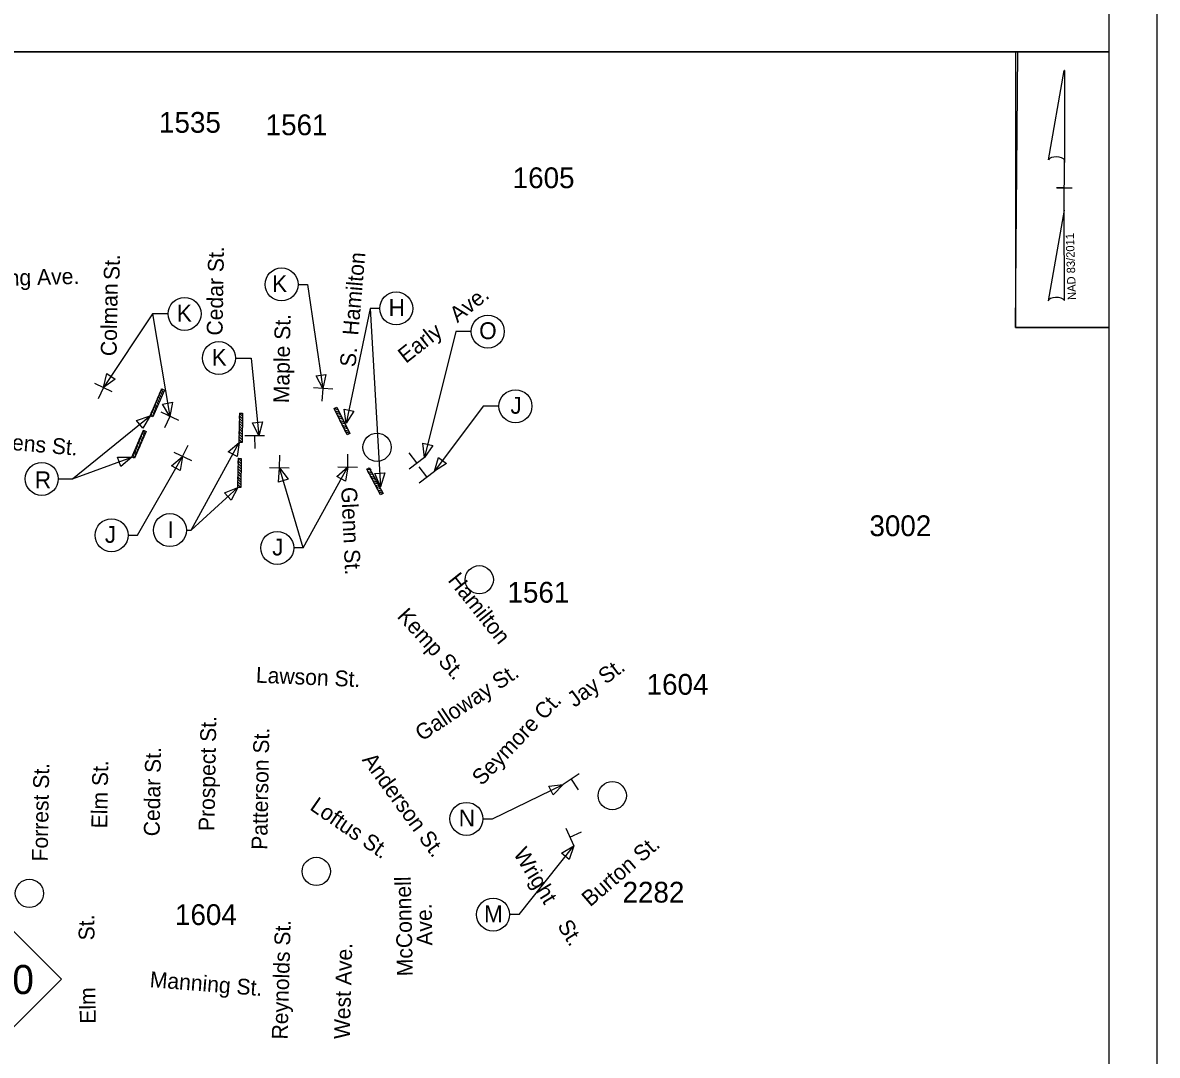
# Model space of a CAD drawing. Extents: x 2157572 to 5059327, y 715220 to 1674494.
# Drawn here: x 2166357 to 2171076, y 724870 to 729165 of the extents above; entities that cross this region are included whole.
import ezdxf

# ---------------------------------------------------------------- set-up
doc = ezdxf.new("R2010")
doc.units = 0
for name, color, linetype in [('Exist Cultural Church Label', 7, 'Continuous'), ('Exist Cultural Recreational Athletic Track', 7, 'Continuous'), ('Exist Road Primary US Shield CELL', 7, 'Continuous'), ('Exist Road Primary US Structure Standard Bridge Number Label', 7, 'Continuous'), ('Exist Road Secondary Type 41 SR Number Label', 7, 'Continuous'), ('Exist Road Secondary Type 51 Divided Label', 7, 'Continuous'), ('Exist Road Secondary Type 51 Undivided 3 Lane Attributed', 7, 'Continuous'), ('Level 51', 7, 'Continuous'), ('Level 53', 7, 'Continuous'), ('Map Preparation County Base Legend Correctional Institution', 7, 'Continuous'), ('Map Preparation County Base Legend Highway Garage or Maintenance Office', 7, 'Continuous'), ('Map Preparation County Base Legend Monument Small Historical Site', 7, 'Continuous'), ('Map Preparation County Base Legend Weight Station', 7, 'Continuous'), ('Map Preparation County North Arrow CELL', 7, 'Continuous'), ('Map Preparation County North Arrow Shadow', 7, 'Continuous'), ('Map Preparation County North Arrow White Shapes', 7, 'Continuous')]:
    doc.layers.add(name, color=color, linetype=linetype)

msp = doc.modelspace()

# ---------------------------------------------------------------- linework, layer by layer
at = {"layer": 'Exist Cultural Church Label'}
for centre in [(2167433.7, 728076), (2167910.5, 727976.1), (2167030.5, 727953.4), (2168291.5, 727880), (2167172.9, 727769.9), (2168406.5, 727569.5), (2166436.2, 727267.1), (2166726.5, 727032.7), (2166969.2, 727054.1), (2167415.6, 726980.1), (2168202.3, 725853.4), (2168313.1, 725455)]:
    msp.add_circle(centre, 68.6, dxfattribs=at)
at = {"layer": 'Exist Road Secondary Type 41 SR Number Label'}
for p, q in [((2166887.1, 727529.6), (2166935.1, 727641.1)), ((2166946.1, 727636.4), (2166898.1, 727524.9)), ((2166917.7, 727601.1), (2166922, 727611.1)), ((2166922, 727611.1), (2166928.4, 727595.3)), ((2166926.3, 727621.2), (2166930.6, 727631.2)), ((2166932.7, 727605.4), (2166926.3, 727621.2)), ((2166930.6, 727631.2), (2166937.1, 727615.4)), ((2166937.1, 727615.4), (2166932.7, 727605.4)), ((2166934.9, 727641.2), (2166946.1, 727636.4)), ((2166941.4, 727625.4), (2166934.9, 727641.2)), ((2166935.1, 727641.1), (2166946.1, 727636.4)), ((2166946.1, 727636.4), (2166941.4, 727625.4)), ((2166900.4, 727560.9), (2166904.7, 727571)), ((2166906.7, 727545), (2166900.4, 727560.9)), ((2166904.7, 727571), (2166911.1, 727555)), ((2166909, 727581), (2166913.3, 727591)), ((2166915.5, 727565.2), (2166909, 727581)), ((2166913.3, 727591), (2166919.8, 727575.2)), ((2166919.8, 727575.2), (2166915.5, 727565.2)), ((2166924.1, 727585.3), (2166917.7, 727601.1)), ((2166928.4, 727595.3), (2166924.1, 727585.3)), ((2167652, 727559.6), (2167662.9, 727565)), ((2167668.2, 727554.3), (2167652, 727559.6)), ((2167652.2, 727559.7), (2167662.9, 727565)), ((2167706.2, 727451), (2167652.2, 727559.7)), ((2167662.9, 727565), (2167668.2, 727554.3)), ((2167662.9, 727565), (2167716.9, 727456.3)), ((2166898.1, 727524.9), (2166887.1, 727529.6)), ((2166891.7, 727540.9), (2166896, 727550.9)), ((2166898.1, 727524.9), (2166891.7, 727540.9)), ((2166896, 727550.9), (2166902.4, 727534.9)), ((2166902.4, 727534.9), (2166898.1, 727524.9)), ((2166911.1, 727555), (2166906.7, 727545)), ((2167257.2, 727419.2), (2167259.6, 727540.6)), ((2167258.9, 727518.8), (2167259.2, 727529.7)), ((2167270.9, 727506.6), (2167258.9, 727518.8)), ((2167259.2, 727529.7), (2167271.1, 727517.5)), ((2167259.4, 727540.7), (2167271.5, 727540.4)), ((2167271.3, 727528.5), (2167259.4, 727540.7)), ((2167259.6, 727540.6), (2167271.5, 727540.4)), ((2167271.5, 727540.4), (2167269.2, 727419)), ((2167271.1, 727517.5), (2167270.9, 727506.6)), ((2167271.5, 727540.4), (2167271.3, 727528.5)), ((2167656.9, 727549.8), (2167673.1, 727544.5)), ((2167661.7, 727540.1), (2167656.9, 727549.8)), ((2167677.9, 727534.8), (2167661.7, 727540.1)), ((2167666.6, 727530.3), (2167682.8, 727525)), ((2167671.5, 727520.5), (2167666.6, 727530.3)), ((2167687.7, 727515.2), (2167671.5, 727520.5)), ((2167673.1, 727544.5), (2167677.9, 727534.8)), ((2167676.3, 727510.7), (2167692.5, 727505.4)), ((2167681.2, 727500.9), (2167676.3, 727510.7)), ((2167682.8, 727525), (2167687.7, 727515.2)), ((2166811.1, 727357.8), (2166859.2, 727469.4)), ((2166870.1, 727464.6), (2166822.1, 727353.1)), ((2166859, 727469.4), (2166870.1, 727464.6)), ((2166865.4, 727453.6), (2166859, 727469.4)), ((2166859.2, 727469.4), (2166870.1, 727464.6)), ((2166870.1, 727464.6), (2166865.4, 727453.6)), ((2167257.7, 727453.3), (2167257.9, 727464.2)), ((2167257.9, 727464.2), (2167269.8, 727451.8)), ((2167258.1, 727475.1), (2167258.3, 727486)), ((2167270, 727462.9), (2167258.1, 727475.1)), ((2167258.3, 727486), (2167270.2, 727473.8)), ((2167258.5, 727497), (2167258.7, 727507.9)), ((2167270.5, 727484.8), (2167258.5, 727497)), ((2167258.7, 727507.9), (2167270.7, 727495.7)), ((2167270.2, 727473.8), (2167270, 727462.9)), ((2167270.7, 727495.7), (2167270.5, 727484.8)), ((2167697.4, 727495.6), (2167681.2, 727500.9)), ((2167686, 727491.1), (2167702.3, 727485.6)), ((2167690.9, 727481.3), (2167686, 727491.1)), ((2167707.2, 727475.9), (2167690.9, 727481.3)), ((2167692.5, 727505.4), (2167697.4, 727495.6)), ((2167695.8, 727471.5), (2167712.1, 727466.1)), ((2167700.6, 727461.8), (2167695.8, 727471.5)), ((2167702.3, 727485.6), (2167707.2, 727475.9)), ((2167712.1, 727466.1), (2167716.9, 727456.3)), ((2166833, 727409.2), (2166837.4, 727419.3)), ((2166837.4, 727419.3), (2166843.8, 727403.5)), ((2166841.7, 727429.3), (2166846, 727439.3)), ((2166848.1, 727413.5), (2166841.7, 727429.3)), ((2166846, 727439.3), (2166852.5, 727423.5)), ((2166852.5, 727423.5), (2166848.1, 727413.5)), ((2166850.3, 727449.4), (2166854.6, 727459.4)), ((2166856.8, 727433.6), (2166850.3, 727449.4)), ((2166854.6, 727459.4), (2166861.1, 727443.6)), ((2166861.1, 727443.6), (2166856.8, 727433.6)), ((2167269.2, 727419), (2167257.2, 727419.2)), ((2167257.3, 727431.4), (2167257.5, 727442.3)), ((2167269.2, 727419), (2167257.3, 727431.4)), ((2167257.5, 727442.3), (2167269.4, 727429.9)), ((2167269.6, 727440.9), (2167257.7, 727453.3)), ((2167269.4, 727429.9), (2167269.2, 727419)), ((2167269.8, 727451.8), (2167269.6, 727440.9)), ((2167716.9, 727456.3), (2167700.6, 727461.8)), ((2167716.9, 727456.3), (2167706.2, 727451)), ((2166815.8, 727369.1), (2166820.1, 727379.1)), ((2166822.1, 727353.1), (2166815.8, 727369.1)), ((2166820.1, 727379.1), (2166826.4, 727363.1)), ((2166824.4, 727389.1), (2166828.7, 727399.2)), ((2166830.8, 727373.2), (2166824.4, 727389.1)), ((2166828.7, 727399.2), (2166835.1, 727383.2)), ((2166835.1, 727383.2), (2166830.8, 727373.2)), ((2166839.5, 727393.4), (2166833, 727409.2)), ((2166843.8, 727403.5), (2166839.5, 727393.4)), ((2166822.1, 727353.1), (2166811.1, 727357.8)), ((2166826.4, 727363.1), (2166822.1, 727353.1)), ((2167251.8, 727231.5), (2167254.1, 727352.9)), ((2167253.5, 727331), (2167253.7, 727342)), ((2167265.4, 727318.9), (2167253.5, 727331)), ((2167253.7, 727342), (2167265.6, 727329.8)), ((2167253.9, 727352.9), (2167266.1, 727352.7)), ((2167265.8, 727340.7), (2167253.9, 727352.9)), ((2167254.1, 727352.9), (2167266.1, 727352.7)), ((2167266.1, 727352.7), (2167263.7, 727231.3)), ((2167265.6, 727329.8), (2167265.4, 727318.9)), ((2167266.1, 727352.7), (2167265.8, 727340.7)), ((2167252.2, 727265.5), (2167252.4, 727276.4)), ((2167252.4, 727276.4), (2167264.4, 727264)), ((2167252.6, 727287.3), (2167252.8, 727298.3)), ((2167264.6, 727275.2), (2167252.6, 727287.3)), ((2167252.8, 727298.3), (2167264.8, 727286.1)), ((2167253.1, 727309.2), (2167253.3, 727320.1)), ((2167265, 727297), (2167253.1, 727309.2)), ((2167253.3, 727320.1), (2167265.2, 727307.9)), ((2167264.8, 727286.1), (2167264.6, 727275.2)), ((2167265.2, 727307.9), (2167265, 727297)), ((2167787.9, 727308.1), (2167798.6, 727313.8)), ((2167804.3, 727303.3), (2167787.9, 727308.1)), ((2167788.1, 727308.2), (2167798.6, 727313.8)), ((2167845.7, 727201.2), (2167788.1, 727308.2)), ((2167793.1, 727298.4), (2167809.5, 727293.7)), ((2167798.3, 727288.8), (2167793.1, 727298.4)), ((2167814.7, 727284.1), (2167798.3, 727288.8)), ((2167798.6, 727313.8), (2167804.3, 727303.3)), ((2167798.6, 727313.8), (2167856.2, 727206.9)), ((2167803.5, 727279.2), (2167819.9, 727274.4)), ((2167808.7, 727269.6), (2167803.5, 727279.2)), ((2167809.5, 727293.7), (2167814.7, 727284.1)), ((2167251.8, 727243.6), (2167252, 727254.6)), ((2167263.7, 727231.3), (2167251.8, 727243.6)), ((2167263.7, 727231.3), (2167251.8, 727231.5)), ((2167252, 727254.6), (2167263.9, 727242.2)), ((2167264.1, 727253.1), (2167252.2, 727265.5)), ((2167263.9, 727242.2), (2167263.7, 727231.3)), ((2167264.4, 727264), (2167264.1, 727253.1)), ((2167825, 727264.8), (2167808.7, 727269.6)), ((2167813.8, 727259.9), (2167830.2, 727255.2)), ((2167819, 727250.3), (2167813.8, 727259.9)), ((2167835.4, 727245.6), (2167819, 727250.3)), ((2167819.9, 727274.4), (2167825, 727264.8)), ((2167824.2, 727240.7), (2167840.7, 727235.8)), ((2167829.4, 727231.1), (2167824.2, 727240.7)), ((2167845.8, 727226.1), (2167829.4, 727231.1)), ((2167830.2, 727255.2), (2167835.4, 727245.6)), ((2167840.7, 727235.8), (2167845.8, 727226.1)), ((2167834.6, 727221.5), (2167851, 727216.5)), ((2167839.7, 727211.8), (2167834.6, 727221.5)), ((2167856.2, 727206.9), (2167839.7, 727211.8)), ((2167856.2, 727206.9), (2167845.7, 727201.2)), ((2167851, 727216.5), (2167856.2, 727206.9))]:
    msp.add_line(p, q, dxfattribs=at)
at = {"layer": 'Exist Road Secondary Type 51 Divided Label'}
msp.add_lwpolyline([(2157571.9, 722288.7), (2171075.9, 722288.7), (2171075.9, 731088.6), (2157571.9, 731088.6)], close=True, dxfattribs=at)
at = {"layer": 'Exist Road Secondary Type 51 Undivided 3 Lane Attributed'}
msp.add_lwpolyline([(2170485.5, 727897.1), (2170495.8, 729042.7), (2158875.9, 729042.7), (2158875.9, 722488.7), (2166434.4, 722488.7), (2166434.4, 723622.8), (2170875.9, 723622.8), (2170875.9, 727897.1)], close=True, dxfattribs=at)
at = {"layer": 'Level 51'}
for p, q in [((2167502.4, 728076), (2167542, 728076)), ((2167542, 728076), (2167605.9, 727643.4)), ((2166896.7, 727953.4), (2166692.9, 727647.1)), ((2166961.9, 727953.4), (2166896.7, 727953.4)), ((2166896.7, 727953.4), (2166969, 727526.9)), ((2167802.2, 727976.1), (2167702.2, 727498.5)), ((2167841.8, 727976.1), (2167802.2, 727976.1)), ((2167802.2, 727976.1), (2167845.8, 727234.9)), ((2168157.8, 727880), (2168028.7, 727357.8)), ((2168222.9, 727880), (2168157.8, 727880)), ((2167241.5, 727769.9), (2167306.7, 727769.9)), ((2167306.7, 727769.9), (2167339.3, 727447)), ((2168272.7, 727569.5), (2168070, 727299.9)), ((2168337.8, 727569.5), (2168272.7, 727569.5)), ((2166563.8, 727267.1), (2166887.1, 727529.6)), ((2167057, 727054.1), (2167257.2, 727419.2)), ((2166563.8, 727267.1), (2166811.1, 727357.8)), ((2166834.7, 727032.7), (2167022.3, 727360.6)), ((2167523.9, 726980.1), (2167424.9, 727313.4)), ((2167523.9, 726980.1), (2167708.7, 727316.9)), ((2166504.9, 727267.1), (2166563.8, 727267.1)), ((2167057, 727054.1), (2167251.8, 727231.5)), ((2167037.8, 727054.1), (2167057, 727054.1)), ((2166795.1, 727032.7), (2166834.7, 727032.7)), ((2167523.9, 726980.1), (2167484.3, 726980.1)), ((2168310.5, 725853.4), (2168604.4, 725995.7)), ((2168270.9, 725853.4), (2168310.5, 725853.4)), ((2168421.4, 725455), (2168648.6, 725741.1)), ((2168421.4, 725455), (2168381.8, 725455))]:
    msp.add_line(p, q, dxfattribs=at)
for points in [[(2166706.4, 727705.3), (2166741.1, 727682.5), (2166692.9, 727647.1)], [(2167577.2, 727695.8), (2167618.2, 727701.8), (2167605.9, 727643.4)], [(2166938.9, 727578.6), (2166979.8, 727585.7), (2166969, 727526.9)], [(2166856.7, 727478.2), (2166830.5, 727510.4), (2166887.1, 727529.6)], [(2167693.4, 727557.6), (2167734, 727549.1), (2167702.2, 727498.5)], [(2167312.8, 727500.5), (2167354, 727504.9), (2167339.3, 727447)], [(2167248.5, 727360.1), (2167212.1, 727380.1), (2167257.2, 727419.2)], [(2168021.8, 727416.2), (2168062.1, 727406.5), (2168028.8, 727356.9)], [(2166765.7, 727319), (2166751.4, 727358), (2166811.1, 727357.8)], [(2167012.5, 727301.6), (2166976.5, 727322.2), (2167022.3, 727360.6)], [(2168086.5, 727356.4), (2168119.8, 727331.6), (2168069.7, 727299)], [(2167460.9, 727265.7), (2167421.2, 727253.7), (2167424.9, 727313.4)], [(2167700.1, 727257.7), (2167663.7, 727277.6), (2167708.7, 727316.9)], [(2167821.8, 727289.6), (2167863.2, 727292), (2167845.8, 727234.9)], [(2167224.3, 727178.4), (2167196.4, 727209.1), (2167251.8, 727231.5)], [(2168563, 725952.6), (2168544.9, 725989.9), (2168604.4, 725995.7)], [(2168630, 725684.3), (2168597.5, 725710.1), (2168648.6, 725741.1)]]:
    msp.add_lwpolyline(points, close=True, dxfattribs=at)
for centre in [(2167830.6, 727398.6), (2168255.9, 726847.7), (2168809.1, 725949.9), (2167578.2, 725634.9), (2166385, 725543.6)]:
    msp.add_circle(centre, 58.7, dxfattribs=at)
at = {"layer": 'Map Preparation County Base Legend Highway Garage or Maintenance Office'}
for centre in [(2167433.7, 728076), (2167910.5, 727976.1), (2167030.5, 727953.4), (2168291.5, 727880), (2167172.9, 727769.9), (2168406.5, 727569.5), (2166436.2, 727267.1), (2166726.5, 727032.7), (2166726.5, 727032.7), (2166969.2, 727054.1), (2167415.6, 726980.1), (2168202.3, 725853.4), (2168313.1, 725455)]:
    msp.add_circle(centre, 68.6, dxfattribs=at)
at = {"layer": 'Map Preparation County Base Legend Monument Small Historical Site'}
msp.add_lwpolyline([(2166058.5, 725186.7), (2166288.7, 725416.9), (2166518.9, 725186.7), (2166288.7, 724956.4)], close=True, dxfattribs=at)
at = {"layer": 'Map Preparation County North Arrow CELL'}
for p, q in [((2170623.4, 728594.8), (2170688.9, 728965)), ((2170689.3, 728965), (2170688.9, 728965)), ((2170689.3, 728965), (2170688.9, 728965)), ((2170689.3, 728965), (2170689.3, 728583.2)), ((2170689.2, 728385.2), (2170689.3, 728594.4)), ((2170689.3, 728583.2), (2170689.3, 728594)), ((2170657.3, 728477.8), (2170656.9, 728477.8)), ((2170685.7, 728477.8), (2170657.3, 728477.8)), ((2170657.7, 728477.8), (2170721.6, 728477.8)), ((2170689.2, 728385.2), (2170622.5, 728007.8)), ((2170689.6, 728009.4), (2170689.2, 728385.2))]:
    msp.add_line(p, q, dxfattribs=at)
for centre, start_param, end_param in [((2170656.4, 728590.9), 0.216388, 2.908219), ((2170656.4, 728006.5), 0.201328, 3.141593)]:
    msp.add_ellipse(centre, major_axis=(33.8, -0.2), ratio=0.461098, start_param=start_param, end_param=end_param, dxfattribs=at)
at = {"layer": 'Map Preparation County North Arrow Shadow'}
for p, q in [((2166729.8, 727629.7), (2166656.6, 727664.2)), ((2166692.9, 727647.1), (2166670.5, 727599.6)), ((2167646.6, 727640), (2167565.9, 727646.6)), ((2167605.9, 727643.4), (2167601.6, 727591)), ((2167005.9, 727509.5), (2166932.7, 727544.1)), ((2166969, 727526.9), (2166946.6, 727479.4)), ((2167362.5, 727446.4), (2167281.5, 727445.9)), ((2167321.7, 727446.1), (2167322, 727393.6)), ((2166985.5, 727378.1), (2167058.6, 727343.3)), ((2167022.3, 727360.6), (2167044.9, 727408)), ((2167708.7, 727316.9), (2167709.6, 727369.4)), ((2167996.7, 727333.5), (2167965, 727375.3)), ((2167424.9, 727313.4), (2167425.8, 727365.8)), ((2167964.1, 727308.9), (2168028.7, 727357.8)), ((2167384.1, 727314.1), (2167465.1, 727312.7)), ((2167667.8, 727317.6), (2167748.8, 727316.2)), ((2168005.4, 727251), (2168070, 727299.9)), ((2168038, 727275.7), (2168006.2, 727317.5)), ((2168672, 726040.4), (2168604.4, 725995.7)), ((2168637.9, 726017.9), (2168666.9, 725974.1)), ((2168616, 725815.2), (2168648.6, 725741.1)), ((2168632.4, 725777.9), (2168680.4, 725799))]:
    msp.add_line(p, q, dxfattribs=at)
at = {"layer": 'Map Preparation County North Arrow White Shapes'}
msp.add_line((2158905.6, 729042.7), (2170875.9, 729042.7), dxfattribs=at)
for points in [[(2170875.9, 730888.7), (2158875.9, 730888.7), (2158875.9, 722488.7), (2170875.9, 722488.7)], [(2170875.9, 729042.7), (2170485.5, 729042.7), (2170485.5, 727897.1), (2170875.9, 727897.1)]]:
    msp.add_lwpolyline(points, close=True, dxfattribs=at)

# ---------------------------------------------------------------- texts
at = {"layer": 'Exist Cultural Recreational Athletic Track'}
for s, height, rotation, p in [('Cedar St.', 65.68, 89.0256, (2167188, 727862.9)), ('St.', 65.68, 89.0256, (2166759.6, 728093.8)), ('Irving Ave.', 65.681, 1.545, (2166178.4, 728067.1)), ('Colman', 65.68, 89.0256, (2166747.4, 727777.4)), ('Early   Ave.', 65.681, 38.263, (2167950.6, 727745.1)), ('Maple St.', 65.68, 89.0256, (2167464.9, 727581.6)), ('Givens St.', 65.68, 355.0653, (2166179.3, 727398.8)), ('Glenn St.', 65.68, 272.6342, (2167681.4, 727232)), ('Kemp St.', 65.68, 312.1703, (2167910.9, 726693.5)), ('Lawson St.', 65.68, 357.5448, (2167325.9, 726420)), ('Galloway St.', 65.681, 33.767, (2168017.3, 726174.1)), ('Jay St.', 65.68, 36.6294, (2168652.6, 726314.3)), ('Seymore Ct.', 65.681, 46.4678, (2168266.4, 725988.2)), ('Prospect St.', 65.681, 89.0165, (2167154.3, 725802.1)), ('Patterson St.', 65.681, 89.0165, (2167374.1, 725724.1)), ('Cedar St.', 65.68, 89.0165, (2166926.3, 725780.4)), ('Anderson St.', 65.681, 306.0035, (2167766, 726098.3)), ('Forrest St.', 65.681, 89.0165, (2166460.7, 725675.7)), ('Elm St.', 65.68, 89.0165, (2166708.2, 725813.5)), ('Loftus St.', 65.68, 325.4435, (2167547.2, 725894.3)), ('Wright    St.', 65.681, 301.4599, (2168395.4, 725709.1)), ('Burton St.', 65.68, 40.7469, (2168717.1, 725484.9)), ('McConnell', 65.68, 91.2388, (2167979.7, 725199.4)), (' Ave.', 65.68, 91.2388, (2168061.8, 725302.1)), ('Elm        St.', 65.681, 90.8349, (2166660.9, 725001.9)), ('Reynolds St.', 65.681, 88.4475, (2167458.5, 724935.1)), ('West Ave.', 65.68, 88.4475, (2167717.1, 724936.6)), ('Manning St.', 65.681, 355.4027, (2166883.9, 725154))]:
    msp.add_text(s, height=height, rotation=rotation, dxfattribs=at).set_placement(p)
at = {"layer": 'Exist Road Primary US Shield CELL'}
for s, height, rotation, p in [('S.  Hamilton', 65.681, 85.0483, (2167741.2, 727730.6)), ('Hamilton', 65.68, 308.6035, (2168122.5, 726844.8))]:
    msp.add_text(s, height=height, rotation=rotation, dxfattribs=at).set_placement(p)
at = {"layer": 'Exist Road Primary US Structure Standard Bridge Number Label'}
for s, p in [('K', (2167394.7, 728044)), ('K', (2166997.8, 727921.5)), ('H', (2167878.9, 727944.7)), ('O', (2168255.5, 727848.6)), ('K', (2167142.9, 727738.1)), ('J', (2168385.6, 727538.1)), ('R', (2166407.7, 727228.3)), ('J', (2166698.8, 727001.3)), ('J', (2167394.7, 726948.7)), ('N', (2168170.7, 725822)), ('M', (2168275.8, 725423.6))]:
    msp.add_text(s, height=70, dxfattribs=at).set_placement(p)
msp.add_text('I', height=70, rotation=360, dxfattribs=at).set_placement((2166959.5, 727020.9))
at = {"layer": 'Level 53'}
for s, p in [('1535', (2166924.1, 728706.8)), ('1561', (2167367.6, 728696.6)), ('1605', (2168395, 728476.4)), ('3002', (2169878.7, 727029.2)), ('1561', (2168373.3, 726752.5)), ('1604', (2168951.9, 726369.5)), ('2282', (2168851.8, 725505.2)), ('1604', (2166990.5, 725411.8))]:
    msp.add_text(s, height=86.42, dxfattribs=at).set_placement(p)
at = {"layer": 'Map Preparation County Base Legend Correctional Institution'}
msp.add_text('NAD 83/2011', height=34.697, rotation=91.8545, dxfattribs=at).set_placement((2170738, 728011.9))
at = {"layer": 'Map Preparation County Base Legend Weight Station'}
msp.add_text('770', height=120.99, dxfattribs=at).set_placement((2166133.9, 725124.7))

doc.saveas('drawing.dxf')
